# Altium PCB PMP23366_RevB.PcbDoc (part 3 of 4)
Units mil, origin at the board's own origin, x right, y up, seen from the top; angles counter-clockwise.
Board outline 6500 x 4250 mil, 4 copper layers (Top Layer 1, Inner Layer 2, Inner Layer 3, Bottom Layer 1), stack 75.824 mil thick; 370 components, 218 nets, 1221 pads, 351 vias.
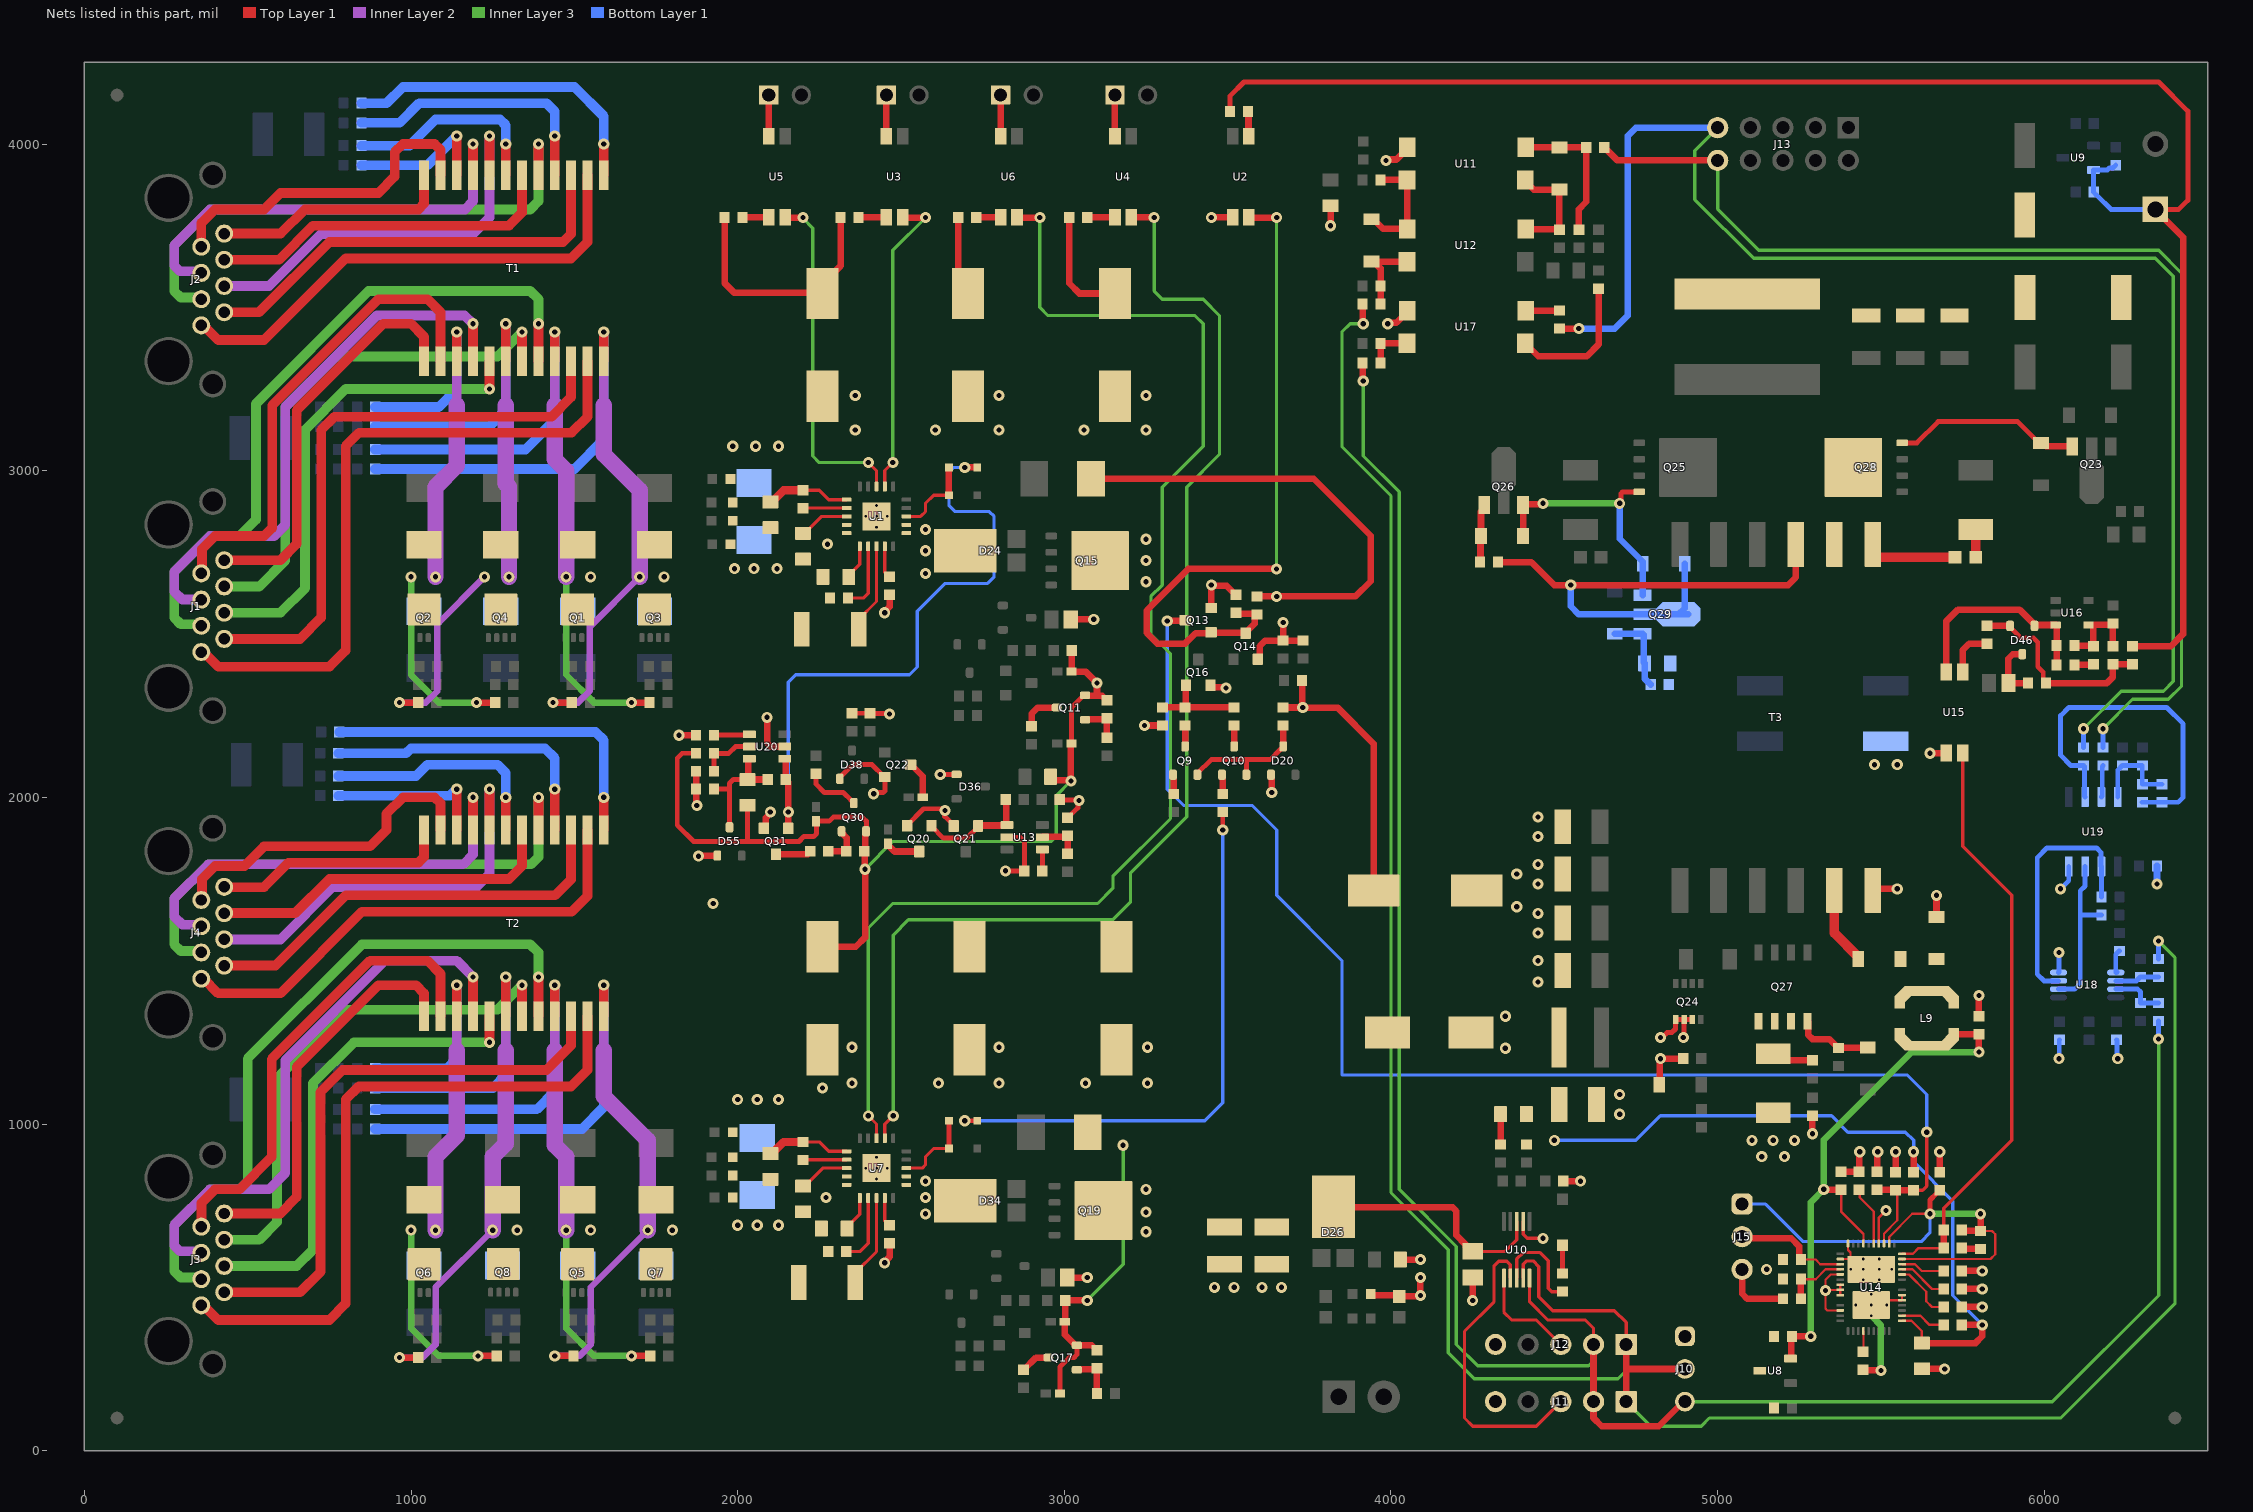
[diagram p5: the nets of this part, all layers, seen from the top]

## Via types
v1: diameter 34, hole 16, Top Layer 1 to Bottom Layer 1, tented both sides, 307 vias
v2: diameter 19.68, hole 7.87, Top Layer 1 to Bottom Layer 1, 23 vias
v3: diameter 34, hole 16, Top Layer 1 to Bottom Layer 1, 21 vias

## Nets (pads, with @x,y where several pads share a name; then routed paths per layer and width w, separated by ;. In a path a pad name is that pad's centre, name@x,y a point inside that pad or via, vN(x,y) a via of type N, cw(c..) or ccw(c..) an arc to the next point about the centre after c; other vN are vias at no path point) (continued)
NetC73_1: C73.1 C94.2 D51.1 Q28.5 Q28.6 Q28.7 Q28.8 Q28.9@5415.39,3010 Q29.2 Q29.4 R92.2 R132.1 T3.7 T3.8 T3.9 | length 1934.9
  Top Layer 1 w20: R92.2@4327.56,2720 4430,2720 4500,2650 v1(4550.47,2650) 5215.91,2650 5239.06,2673.15 T3.9@5239.06,2774.53
  Top Layer 1 w30: T3.7@5475.28,2774.53 5475.28,2745.59 5485.87,2735 C73.1@5727.01,2735
  Bottom Layer 1 w20: v1(4550.47,2650) 4550,2649.53 4550,2585 4575,2560 Q29.2@4778.07,2560 Q29.4@4880.43,2560 ; D51.1@4899.47,2715 4899.47,2579.04 Q29.4@4880.43,2560 ; Q29.4@4909.96,2560 Q29.4@4880.43,2560
NetC73_2: C73.2 R96.1 | length 85
  Top Layer 1 w30: C73.2@5790,2735 R96.1@5790,2820
NetC76_1: C76.1 U14.33 | length 136.6
  Top Layer 1 w7: U14.33@5564.49,570.87 5604.13,570.87 5625,550 C76.1@5692.44,550
NetC79_1: C79.1 J15.2 U14.3 | length 355.9
  Top Layer 1 w7: C79.1@5255,585 5300,585 5314.13,570.87 U14.3@5375.51,570.87
  Top Layer 1 w20: J15.2@5075,655 5080,650 5225,650 5249.25,625.75 5249.25,590.75 C79.1@5255,585
NetC82_2: C82.2 U14.40 | length 183.4
  Top Layer 1 w7: C82.2@5433,798.7 5435,796.71 5435,775.15 5477.87,732.28 U14.40@5477.87,633.86
NetC83_1: C83.1 C85.1 R104.2 R111.2 U16.4 | length 253.6
  Top Layer 1 w20: C83.1@6092.56,2465 6093.78,2463.78 6148.78,2463.78 C85.1@6150,2462.56 6150,2524.53 6153.9,2528.43 6205.98,2528.43 R111.2@6210,2532.44 R104.2@6210,2462.56
NetC83_2: C83.2 D46.1 R109.1 U15.2 U16.3 | length 651.1
  Top Layer 1 w20: U15.2@5700,2384.02 5699.44,2384.57 5699.44,2538.35 5736.1,2575 5923.94,2575 5970,2528.94 D46.1@5970,2525 ; D46.1@5971.81,2527.6 U16.3@6034.8,2527.6 6036.61,2527.6 6037.44,2526.77 C83.2@6037.44,2465 R109.1@6037.44,2405
NetC84_1: C84.1 R103.1 | length 58.5
  Top Layer 1 w20: C84.1@5747.56,620 5748.84,618.72 5803.72,618.72 R103.1@5805,617.44
NetC84_2: C84.2 R105.1 U14.35 U15.4 | length 1799.3
  Top Layer 1 w7: U14.35@5564.49,602.36 5597.36,602.36 5615,620 C84.2@5692.44,620
  Top Layer 1 w10: R105.1@5692.44,675 5692.44,742.44 5900,950 5900,1700 5750,1850 U15.4@5750,2135.98
  Top Layer 1 w20: C84.2@5692.44,620 R105.1@5692.44,675
NetC85_2: C85.2 R109.2 | length 58.5
  Top Layer 1 w20: R109.2@6092.56,2405 6093.78,2406.22 6148.78,2406.22 C85.2@6150,2407.44
NetC86_2: C86.2 D46.3 R107.2 | length 182.8
  Top Layer 1 w20: D46.3@5932.6,2438.39 5903.78,2438.39 5890,2424.61 C86.2@5890,2350 R107.2@5949.88,2350
NetC89_2: C89.2 D55.3 R130.2 R134.1 U20.6 | length 371.1
  Top Layer 1 w15: C89.2@1927.56,2025 1974.91,2025 1975,2025.09 ; D55.3@1975,1908.31 1975,2025.09 ; R130.2@2030.32,2054.69 1986.5,2054.69 1975,2043.19 1975,2025.09
  Top Layer 1 w20: U20.6@2035.87,2118.15 2034.74,2118.15 2032.93,2116.34 2032.93,2057.3 2030.32,2054.69 2092.13,2054.69 R134.1@2092.44,2055
NetC91_2: C91.2 R118.1 R123.2 R124.2 U19.8 | length 280.4
  Bottom Layer 1 w15: U19.8@6225,2001.3 6225,2083.43 6239.02,2097.44 R118.1@6240,2097.44 C91.2@6300,2097.44 R123.2@6300,2040 R124.2@6360,2040
NetC92_1: C92.1 U20.4 | length 109.5
  Top Layer 1 w15: C92.1@1927.56,2190 1929.04,2191.48 2034.39,2191.48 U20.4@2035.87,2192.95
NetC93_1: C93.1 U13.4 | length 65.6
  Top Layer 1 w15: C93.1@2932.56,1775 C93.1@2932.56,1775 2932.61,1840.5 U13.4@2932.66,1840.55
NetC94_1: C94.1 D52.1 Q29.1 R132.2 | length 251.8
  Bottom Layer 1 w20: D52.1@4685,2500.53 4685.21,2500.74 4770.2,2500.74 4773.27,2497.67 4773.27,2413.07 R132.2@4776.34,2410 4776.34,2363.54 4788.15,2351.73 4789.13,2351.73 4794.88,2345.98 C94.1@4794.88,2345
NetD20_3: D20.3 Q9.2 Q10.2 R33.1 | length 400.7
  Top Layer 1 w15: Q9.2@3407.4,2069.25 3407.4,2073.19 3449.88,2115.67 3555,2115.67 ; Q10.2@3557.4,2069.25 3557.4,2113.27 3555,2115.67 ; D20.3@3661.75,2147.62 3629.8,2115.67 3555,2115.67
  Top Layer 1 w20: D20.3@3670,2155.87 R33.1@3670,2220
NetD22_1: D22.1 D53.1 U1.13 | length 256.7
  Top Layer 1 w10: U1.13@2516.54,2860 2560,2860 2575,2875 2575,2900 2600,2925 D22.1@2646.69,2925
  Top Layer 1 w20: D22.1@2646.69,2925 D53.1@2646.69,3010
NetD31_1: D31.1 D54.1 U7.13 | length 254.7
  Top Layer 1 w10: U7.13@2516.54,865 2565,865 2575,875 2575,900 2600,925 D31.1@2646.69,925
  Top Layer 1 w15: D31.1@2646.69,925 D54.1@2646.69,1010
NetD35_1: D35.1 R83.1 | length 89.2
  Top Layer 1 w15: R83.1@4525,540 D35.1@4525,629.21
NetD39_2: D39.2 Q23.3 Q28.4 | length 579
  Top Layer 1 w15: Q28.4@5565,3085 5610,3085 5675,3150 5918.46,3150 5984,3084.47 D39.2@5990,3084.47
  Top Layer 1 w20: D39.2@5990,3084.47 5996,3084.47 6005.67,3074.8 Q23.3@6085.94,3074.8
NetD42_1: D42.1 D51.2 Q25.4 Q26.3 Q29.3 | length 793.5
  Top Layer 1 w15: v1(4700,2900) 4703.64,2903.64 4703.64,2929.85 4708.79,2935 Q25.4@4760,2935
  Top Layer 1 w20: D42.1@4404.47,2800 4404.26,2800.21 4404.26,2894.99 Q26.3@4404.06,2895.2 4406.46,2897.6 4462.6,2897.6 v1(4465,2900)
  Inner Layer 3 w20: v1(4465,2900) v1(4700,2900)
  Bottom Layer 1 w20: v1(4700,2900) 4700,2791.54 4770.53,2721 D51.2@4770.53,2715 4770.36,2714.83 4770.36,2619.22 Q29.3@4770.2,2619.06
NetD42_2: D42.2 Q26.1 R92.1 | length 180.8
  Top Layer 1 w20: R92.1@4272.44,2720 4273.99,2721.55 4273.99,2798.45 D42.2@4275.53,2800 4275.53,2874.94 4285.94,2885.35 Q26.1@4285.94,2895.2
NetD43_2: D43.2 Q27.4 R94.2 | length 243.3
  Top Layer 1 w20: Q27.4@5275,1314.88 5277.01,1312.87 5277.01,1272.99 5290,1260 5341.57,1260 5369.02,1232.56 5369.97,1233.51 5459.05,1233.51 D43.2@5460,1234.47
NetD44_1: D44.1 D45.1 L9.2
NetD44_2: D44.2 T3.5 | length 240.9
  Top Layer 1 w30: T3.5@5357.17,1715.47 5357.17,1584.37 5430.53,1511 D44.2@5430.53,1505
NetD46_2: D46.2 R101.2 R104.1 R106.2 R107.1 | length 625
  Top Layer 1 w15: D46.2@5895.2,2525 5895.2,2521.06 5927.68,2488.58 5966.42,2488.58 5980,2475 5980,2400 5996.75,2383.25 5996.75,2358.25 R107.1@6005,2350
  Top Layer 1 w20: R106.2@5825,2525 D46.2@5895.2,2525 ; R107.1@6005,2350 6191.57,2350 6210,2368.43 R104.1@6210,2407.44 R101.2@6270,2407.44
NetD47_1: D47.1 Q22.3 | length 116.6
  Top Layer 1 w20: Q22.3@2529.37,2100 2531.34,2100 2566.65,2064.69 D47.1@2566.65,2000
NetD48_1: D48.1 Q20.3 | length 108.4
  Top Layer 1 w20: D48.1@2460,1858.35 2460,1854.41 2480.2,1834.21 Q20.3@2556.12,1834.21
NetD49_1: D49.1 R77.1 U11.1 U12.4 | length 346.3
  Top Layer 1 w20: U11.1@4411.22,3890 4411.22,3886.06 4436.75,3860.53 D49.1@4515.61,3860.53 R77.1@4515.61,3737.56 4514.39,3738.78 4413.43,3738.78 U12.4@4412.2,3740
NetD49_2: D49.2 R78.1 R79.1 U11.2 | length 448.5
  Top Layer 1 w20: U11.2@4412.2,3990 4412.47,3989.73 4515.34,3989.73 D49.2@4515.61,3989.47 4515.88,3989.73 4597.79,3989.73 R79.1@4598.05,3990 4598.05,3823.05 4575,3800 4575,3738.17 R78.1@4575.61,3737.56
NetD50_1: D50.1 R76.2 U11.4 U12.1 | length 352.9
  Top Layer 1 w20: D50.1@3940.61,3769.47 3946.61,3769.47 3976.08,3740 U12.1@4050,3740 4049.51,3740.49 4049.51,3889.51 U11.4@4049.02,3890 R76.2@3968.17,3890
NetD50_2: D50.2 R80.2 R81.1 U12.2 | length 247.7
  Top Layer 1 w20: D50.2@3940.61,3640.53 3946.61,3640.53 D50.2@3946.88,3640.27 ; R81.1@3968.17,3510 R80.2@3968.17,3565 3968.17,3618.98 D50.2@3946.88,3640.27 ; U12.2@4049.02,3640 4048.75,3640.27 D50.2@3946.88,3640.27
NetJ1_1: J1.1 T1.23 | length 2053.6
  Top Layer 1 w30: J1.1@357.91,2444.84 364.71,2444.84 409.55,2400 750,2400 800,2450 800,3075 841.3,3116.3 1491.3,3116.3 1540,3165 T1.23@1540,3334.92
NetJ1_2: J1.2 T1.22 | length 1815.3
  Top Layer 1 w30: J1.2@427.99,2485 660,2485 725,2550 725,3125 765,3165 1430,3165 1490,3225 T1.22@1490,3334.92
NetJ1_3: J1.3 T1.20 | length 2112.8
  Top Layer 1 w30: T1.20@1390,3334.92 v1(1390,3450)
  Inner Layer 3 w30: J1.3@357.91,2525.16 353.11,2529.96 295.04,2529.96 275,2550 275,2690 385,2800 475,2800 525,2850 525,3205 870,3550 1365,3550 1390,3525 v1(1390,3450)
NetJ1_4: J1.4 T1.17 | length 1464.6
  Top Layer 1 w30: v1(1240,3250) T1.17@1240,3334.92
  Inner Layer 3 w30: J1.4@427.99,2565.31 600.32,2565.31 675,2640 675,3125 800,3250 v1(1240,3250)
NetJ1_5: J1.5 T1.16 | length 1730.4
  Top Layer 1 w30: T1.16@1190,3334.92 v1(1190,3450)
  Inner Layer 2 w30: J1.5@357.91,2605.47 299.53,2605.47 275,2630 275,2690 385,2800 581.42,2800 615,2833.58 615,3195 895,3475 1163.92,3475 1188.92,3450 v1(1190,3450)
NetJ1_6: J1.6 T1.19 | length 1600.2
  Top Layer 1 w30: T1.19@1340,3334.92 v1(1340,3425)
  Inner Layer 3 w30: J1.6@427.99,2645.63 535.63,2645.63 615,2725 615,3195 770,3350 1265,3350 v1(1340,3425)
NetJ1_7: J1.7 T1.14 | length 1508.3
  Top Layer 1 w30: J1.7@357.91,2685.79 360,2687.87 360,2760 400,2800 550,2800 575,2825 575,3200 900,3525 1050,3525 1090,3485 T1.14@1090,3334.92
NetJ1_8: J1.8 T1.13 | length 1243.7
  Top Layer 1 w30: J1.8@427.99,2725.94 600.94,2725.94 650,2775 650,3185 915,3450 1000,3450 1040,3410 T1.13@1040,3334.92
NetJ2_1: J2.1 T1.2 | length 1529.9
  Top Layer 1 w30: J2.1@357.91,3444.84 364.71,3444.84 409.55,3400 550,3400 800,3650 1490,3650 1540,3700 T1.2@1540,3905
NetJ2_2: J2.2 T1.3 | length 1341.6
  Top Layer 1 w30: J2.2@427.99,3485 535,3485 750,3700 1465.35,3700 1490,3724.65 T1.3@1490,3905
NetJ2_3: J2.3 T1.5 | length 1674.1
  Top Layer 1 w30: T1.5@1390,3905 v1(1390,4000)
  Inner Layer 3 w30: J2.3@357.91,3525.16 353.11,3529.96 295.04,3529.96 275,3550 275,3690 385,3800 1365,3800 1390,3825 v1(1390,4000)
NetJ2_4: J2.4 T1.8 | length 1268.9
  Top Layer 1 w30: T1.8@1240,3905 v1(1240,4025)
  Inner Layer 2 w30: J2.4@427.99,3565.31 565.32,3565.31 725,3725 1190,3725 1240,3775 v1(1240,4025)
NetJ2_5: J2.5 T1.9 | length 1395.3
  Top Layer 1 w30: T1.9@1190,3905 v1(1190,4000)
  Inner Layer 2 w30: J2.5@357.91,3605.47 353.11,3610.28 292.57,3610.28 275,3627.85 275,3690 385,3800 1165,3800 1190,3825 v1(1190,4000)
NetJ2_6: J2.6 T1.6 | length 1086.8
  Top Layer 1 w30: J2.6@427.99,3645.63 595.63,3645.63 700,3750 1300,3750 1340,3790 T1.6@1340,3905
NetJ2_7: J2.7 T1.11 | length 1033.1
  Top Layer 1 w30: J2.7@357.91,3685.79 357.91,3757.91 400,3800 550,3800 600,3850 900,3850 950,3900 950,3975 975,4000 1072.43,4000 1090,3982.43 T1.11@1090,3905
NetJ2_8: J2.8 T1.12 | length 737.4
  Top Layer 1 w30: J2.8@427.99,3725.94 600.94,3725.94 675,3800 1022.43,3800 1040,3817.57 T1.12@1040,3905
NetJ3_1: J3.1 T2.23 | length 2048.6
  Top Layer 1 w30: J3.1@357.91,444.84 364.71,444.84 409.55,400 750,400 800,450 800,1075 840,1115 1490,1115 1540,1165 T2.23@1540,1329.96
NetJ3_2: J3.2 T2.22 | length 1786.9
  Top Layer 1 w30: J3.2@427.99,485 660,485 722.44,547.44 722.44,1097.44 790,1165 1415,1165 1490,1240 T2.22@1490,1329.96
NetJ3_3: J3.3 T2.20 | length 2129.5
  Top Layer 1 w30: T2.20@1390,1329.96 v1(1390,1450)
  Inner Layer 3 w30: J3.3@357.91,525.16 353.11,529.96 295.04,529.96 275,550 275,690 385,800 475,800 500,825 500,1200 850,1550 1365,1550 1390,1525 v1(1390,1450)
NetJ3_4: J3.4 T2.17 | length 1474.6
  Top Layer 1 w30: v1(1240,1250) T2.17@1240,1329.96
  Inner Layer 3 w30: J3.4@427.99,565.32 428.31,565 650,565 700,615 700,1125 825,1250 v1(1240,1250)
NetJ3_5: J3.5 T2.16 | length 1747.7
  Top Layer 1 w30: T2.16@1190,1329.96 v1(1190,1450)
  Inner Layer 2 w30: J3.5@357.91,605.47 353.11,610.28 292.57,610.28 275,627.85 275,690 385,800 565,800 615,850 615,1195 920,1500 1140,1500 v1(1190,1450)
NetJ3_6: J3.6 T2.19 | length 1587.6
  Top Layer 1 w30: T2.19@1340,1329.96 v1(1340,1425)
  Inner Layer 3 w30: J3.6@427.99,645.63 535.63,645.63 590,700 590,1140 800,1350 1265,1350 v1(1340,1425)
NetJ3_7: J3.7 T2.14 | length 1433.9
  Top Layer 1 w30: J3.7@357.91,685.79 358.35,686.22 358.35,758.35 400,800 475,800 573.43,898.43 573.43,1198.43 875,1500 1050,1500 1090,1460 T2.14@1090,1329.96
NetJ3_8: J3.8 T2.13 | length 1215.7
  Top Layer 1 w30: J3.8@427.99,725.94 600,725.94 650,775.94 650,1175 900,1425 1015,1425 1040,1400 T2.13@1040,1329.96
NetJ4_1: J4.1 T2.2 | length 1526.3
  Top Layer 1 w30: J4.1@357.91,1444.84 364.71,1444.84 409.55,1400 600,1400 850,1650 1492.26,1650 1540,1697.74 T2.2@1540,1900.04
NetJ4_2: J4.2 T2.3 | length 1322.4
  Top Layer 1 w30: J4.2@427.99,1485 585,1485 800,1700 1441.08,1700 1490,1748.92 T2.3@1490,1900.04
NetJ4_3: J4.3 T2.5 | length 1683.4
  Top Layer 1 w30: T2.5@1390,1900.04 v1(1390,2000)
  Inner Layer 3 w30: J4.3@357.91,1525.16 353.11,1529.96 295.04,1529.96 275,1550 275,1690 380,1795 1367.43,1795 1390,1817.57 v1(1390,2000)
NetJ4_4: J4.4 T2.8 | length 1279.9
  Top Layer 1 w30: T2.8@1240,1900.04 v1(1240,2025)
  Inner Layer 2 w30: J4.4@427.99,1565.32 428.31,1565 600,1565 760,1725 1200,1725 1240,1765 v1(1240,2025)
NetJ4_5: J4.5 T2.9 | length 1396
  Top Layer 1 w30: T2.9@1190,1900.04 v1(1190,2000)
  Inner Layer 2 w30: J4.5@357.91,1605.47 353.11,1610.28 299.72,1610.28 275,1635 275,1690 380,1795 1160,1795 1190,1825 v1(1190,2000)
NetJ4_6: J4.6 T2.6 | length 1081.8
  Top Layer 1 w30: J4.6@427.99,1645.63 645.63,1645.63 750,1750 1300,1750 1340,1790 T2.6@1340,1900.04
NetJ4_7: J4.7 T2.11 | length 1017.6
  Top Layer 1 w30: J4.7@357.91,1685.79 360,1687.87 360,1750 400,1790 490,1790 550,1850 875,1850 925,1900 925,1950 975,2000 1072.43,2000 1090,1982.43 T2.11@1090,1900.04
NetJ4_8: J4.8 T2.12 | length 733.2
  Top Layer 1 w30: J4.8@427.99,1725.94 428.94,1725 550,1725 625,1800 1022.43,1800 1040,1817.57 T2.12@1040,1900.04
NetJ5_1: J5.1 U3.4 | length 126
  Top Layer 1 w20: U3.4@2455,4024.02 J5.1@2455,4150
NetJ6_1: J6.1 U4.4 | length 126
  Top Layer 1 w20: U4.4@3155,4024.02 J6.1@3155,4150
NetJ7_1: J7.1 U5.4 | length 126
  Top Layer 1 w20: U5.4@2095,4024.02 J7.1@2095,4150
NetJ8_1: J8.1 U6.4 | length 126
  Top Layer 1 w20: U6.4@2805,4024.02 J8.1@2805,4150
NetJ11_3: J11.3 U10.2 | length 940.8
  Top Layer 1 w10: U10.2@4365.31,528.39 4365.31,569.68 4355,580 4330,580 4315,565 4315,454.84 4225,364.84 4225,100 4250,75 4445,75 J11.3@4520,150
NetJ12_3: J12.3 U10.1 | length 319.5
  Top Layer 1 w10: U10.1@4345.63,528.39 4345.63,424.37 4370,400 4445,400 J12.3@4520,325
NetJ15_3: J15.3 R100.1 | length 206.1
  Top Layer 1 w20: J15.3@5075,555 5075,480 5090,465 R100.1@5199.88,465
NetQ9_1: Q9.1 R38.2 | length 60.1
  Top Layer 1 w20: Q9.1@3332.6,2069.25 3332.6,2065.31 3335,2062.91 R38.2@3335,2010.12
NetQ9_3: Q9.3 R42.1 | length 64.1
  Top Layer 1 w20: Q9.3@3370,2155.87 R42.1@3370,2220
NetQ10_1: Q10.1 R39.2 | length 60.1
  Top Layer 1 w20: Q10.1@3482.6,2069.25 3482.6,2065.31 3485,2062.91 R39.2@3485,2010.12
NetQ10_3: Q10.3 R43.2 | length 64.1
  Top Layer 1 w20: Q10.3@3520,2155.87 R43.2@3520,2220
NetQ11_1: Q11.1 R35.1 R37.1 | length 122.7
  Top Layer 1 w20: Q11.1@3063.31,2237.6 3065.12,2239.41 3127.28,2239.41 3130,2236.69 R37.1@3130,2182.56
NetQ11_3: Q11.3 R41.2 | length 123.2
  Top Layer 1 w20: R41.2@2900,2217.56 2900,2256.3 2918.7,2275 Q11.3@2976.69,2275
NetQ13_1: Q13.1 Q14.3 R45.1 R51.2 U2.4 | length 2151
  Top Layer 1 w10: U2.4@3565,3775.98 U2.4@3565.98,3775 ; v1(3649.33,2699.29) v1@3650.71,2699.29
  Top Layer 1 w20: R51.2@3525,2565 3527.5,2562.5 3587.5,2562.5 R45.1@3590,2560 3589.02,2560 3583.27,2554.25 3583.27,2532.17 3554.65,2503.54 3450.98,2503.54 Q13.1@3449.37,2505.16 3446.93,2502.72 3401.65,2502.72 3369.61,2470.67 3284.74,2470.67 3252.14,2503.27 3252.14,2571.87 3379.56,2699.29 v1(3649.33,2699.29) ; U2.4@3565.98,3775 v1(3650,3775)
  Inner Layer 3 w10: v1(3649.33,2699.29) 3649.33,3774.33 v1(3650,3775)
NetQ16_1: Q16.1 R42.2 R43.1 R54.2 | length 289.1
  Top Layer 1 w20: R54.2@3300,2275.12 R42.2@3370,2275.12 ; Q16.1@3372.6,2343.19 3371.3,2341.89 3371.3,2276.42 R42.2@3370,2275.12 ; R43.1@3520,2275.12 R42.2@3370,2275.12
NetQ17_1: Q17.1 R59.1 R62.1 | length 141.1
  Top Layer 1 w20: Q17.1@3038.31,247.6 3040.12,249.41 3096.97,249.41 R59.1@3099.94,252.38 ; R62.1@3099.88,175 3099.94,175.06 R59.1@3099.94,252.38 ; R59.1@3100,252.44 R59.1@3099.94,252.38
NetQ17_3: Q17.3 R63.2 | length 92.2
  Top Layer 1 w20: R63.2@2875,247.56 2875.98,247.56 2913.43,285 Q17.3@2951.69,285
NetQ20_1: Q20.1 Q21.1 R86.2 U13.1 | length 343.4
  Top Layer 1 w15: Q20.1@2593.52,1912.95 2593.52,1910.98 2629.51,1875 2700.57,1875 2735.92,1910.35 Q21.1@2735.92,1912.32
  Top Layer 1 w20: Q21.1@2735.92,1912.32 2737.44,1913.84 2822.87,1913.84 2822.68,1914.03 2822.68,1991.24 R86.2@2820.96,1992.95
NetQ27_1: Q27.1 Q27.2 Q27.3 R98.2 R99.1 | length 128.3
  Top Layer 1 w20: R99.1@5170,1215 5190,1195 R98.2@5290,1195
NetQ30_1: Q30.1 R131.1 R133.1 | length 122.6
  Top Layer 1 w20: R133.1@2277.56,1835 R131.1@2332.44,1835 2333.46,1836.02 2333.46,1876.67 2318.13,1892.01 Q30.1@2318.13,1895.94
NetQ30_3: Q30.3 R85.2 | length 174.1
  Top Layer 1 w15: R85.2@2240,2072.44 2240,2040 2265,2015 2323.09,2015 2347.28,1990.81 2351.22,1990.81 2355.53,1986.5 Q30.3@2355.53,1982.56
NetQ31_3: Q31.3 R133.2 | length 109
  Top Layer 1 w20: Q31.3@2117.6,1826.26 2214.68,1826.26 2222.44,1834.02 R133.2@2222.44,1835
NetR1_2: R1.2 T1.1 | length 979.4
  Top Layer 1 w30: T1.1@1590,3905 v1(1590,4000)
  Bottom Layer 1 w30: R1.2@848.62,4125 925,4125 975,4175 1500,4175 1590,4085 v1(1590,4000)
NetR2_2: R2.2 T1.4 | length 821.6
  Top Layer 1 w30: T1.4@1440,3905 v1(1440,4025)
  Bottom Layer 1 w30: R2.2@848.62,4065 965,4065 1025,4125 1415,4125 1440,4100 v1(1440,4025)
NetR11_2: R11.2 T1.7 | length 634.2
  Top Layer 1 w30: T1.7@1290,3905 v1(1290,4000)
  Bottom Layer 1 w30: R11.2@848.62,3995 995,3995 1075,4075 1272.43,4075 1290,4057.43 v1(1290,4000)
NetR12_2: R12.2 T1.10 | length 448.7
  Top Layer 1 w30: T1.10@1140,3905 v1(1140,4025)
  Bottom Layer 1 w30: R12.2@848.62,3935 1050,3935 v1(1140,4025)
NetR17_2: R17.2 T2.1 | length 1095.3
  Top Layer 1 w30: T2.1@1590,1900.04 v1(1590,2000)
  Bottom Layer 1 w30: R17.2@780,2200 1565,2200 1590,2175 v1(1590,2000)
NetR18_2: R18.2 T2.4 | length 901
  Top Layer 1 w30: T2.4@1440,1900.04 v1(1440,2025)
  Bottom Layer 1 w30: R18.2@777.56,2135 985,2135 1000,2150 1410,2150 1440,2120 v1(1440,2025)
NetR27_2: R27.2 T2.7 | length 712.3
  Top Layer 1 w30: T2.7@1290,1900.04 v1(1290,2000)
  Bottom Layer 1 w30: R27.2@777.56,2065 1015,2065 1050,2100 1265,2100 1290,2075 v1(1290,2000)
NetR28_2: R28.2 T2.10 | length 495.7
  Top Layer 1 w30: T2.10@1140,1900.04 v1(1140,2025)
  Bottom Layer 1 w30: R28.2@777.56,2005 1118.92,2005 1138.92,2025 v1(1140,2025)
NetR34_1: R34.1 U1.2 | length 133.8
  Top Layer 1 w10: R34.1@2200,2884.88 2200.71,2885.59 U1.2@2333.46,2885.59
NetR40_1: R40.1 U1.9 | length 100
  Top Layer 1 w10: U1.9@2450.59,2768.46 2450.59,2688.43 2464.02,2675 R40.1@2465,2675
NetR44_1: R44.1 U1.8 | length 276.2
  Top Layer 1 w10: R44.1@2370,2515 2370,2544.53 2425,2599.53 U1.8@2425,2768.46
NetR46_2: R46.2 U1.7 | length 211.9
  Top Layer 1 w10: R46.2@2337.56,2610 2385,2610 2399.41,2624.41 U1.7@2399.41,2768.46
NetR47_2: R47.2 U1.3 | length 155
  Top Layer 1 w10: R47.2@2200,2808.07 2204.92,2808.07 2256.85,2860 U1.3@2333.46,2860
NetR48_2: R48.2 U1.6 | length 107.5
  Top Layer 1 w10: R48.2@2340,2675 2340,2679.92 2373.82,2713.74 U1.6@2373.82,2768.46
NetR53_1: R53.1 U2.1 | length 77
  Top Layer 1 w20: R53.1@3562.56,4100 3563.78,4098.78 3563.78,4025.24 U2.1@3565,4024.02
NetR55_2: R55.2 U3.1 | length 85.4
  Top Layer 1 w20: R55.2@2370,3775 2370.49,3775.49 2454.51,3775.49 U3.1@2455,3775.98
NetR56_2: R56.2 U4.1 | length 85.4
  Top Layer 1 w20: R56.2@3070,3775 3070.49,3775.49 3154.51,3775.49 U4.1@3155,3775.98
NetR57_2: R57.2 U5.1 | length 80.4
  Top Layer 1 w20: R57.2@2015,3775 2015.49,3775.49 2094.51,3775.49 U5.1@2095,3775.98
NetR58_2: R58.2 U6.1 | length 75.4
  Top Layer 1 w20: R58.2@2730,3775 2730.49,3775.49 2804.51,3775.49 U6.1@2805,3775.98
NetR60_1: R60.1 U7.2 | length 133.8
  Top Layer 1 w10: R60.1@2200,889.88 2200.71,890.59 U7.2@2333.46,890.59
NetR64_1: R64.1 U7.9 | length 90
  Top Layer 1 w10: U7.9@2450.59,773.46 2450.59,703.43 2464.02,690 R64.1@2465,690
NetR65_1: R65.1 U7.8 | length 285.4
  Top Layer 1 w10: R65.1@2360,515 2360,544.53 2425,609.53 U7.8@2425,773.46
NetR66_2: R66.2 U7.7 | length 216
  Top Layer 1 w10: R66.2@2332.56,610 2375,610 2399.41,634.41 U7.7@2399.41,773.46
NetR67_2: R67.2 U7.3 | length 156.2
  Top Layer 1 w10: R67.2@2200,810 2204.92,810 2259.92,865 U7.3@2333.46,865
NetR68_2: R68.2 U7.6 | length 109.5
  Top Layer 1 w10: R68.2@2335,680 2335,684.92 2373.82,723.74 U7.6@2373.82,773.46
NetR82_2: R82.2 R116.1 U17.4 | length 140.8
  Top Layer 1 w20: R116.1@3968.17,3330 R82.2@3968.17,3390 U17.4@4049.02,3390
NetR83_2: R83.2 U10.3 | length 306.2
  Top Layer 1 w10: U10.3@4385,528.39 4385,586.85 4404.45,606.3 4456.5,606.3 4481.3,581.5 4481.3,496.8 4491.71,486.38 4523.94,486.38 R83.2@4525,487.44
NetR87_1: R87.1 R89.2 U13.5 | length 134.1
  Top Layer 1 w20: U13.5@2932.66,1877.95 2934.47,1879.76 3007.32,1879.76 R89.2@3010,1882.44 R87.1@3010,1827.56
NetR100_2: R100.2 R102.1 U14.4 | length 193
  Top Layer 1 w7: R102.1@5255,525 5300,525 5330.12,555.12 U14.4@5375.51,555.12
  Top Layer 1 w20: R100.2@5255,465 R102.1@5255,525
NetR106_1: R106.1 U15.1 | length 149.2
  Top Layer 1 w20: U15.1@5750,2384.02 5750,2450 5769.88,2469.88 R106.1@5825,2469.88
NetR108_2: R108.2 U14.17 | length 64.3
  Top Layer 1 w7: R108.2@5445.06,302.42 5446.38,303.74 U14.17@5446.38,366.14
NetR110_2: R110.2 U14.24 | length 139.7
  Top Layer 1 w7: U14.24@5564.49,413.39 5619.96,413.39 5648.35,385 R110.2@5692.44,385
NetR112_2: R112.2 U14.31 | length 185.9
  Top Layer 1 w7: U14.31@5564.49,539.37 5585.63,539.37 5638.82,486.18 5638.82,457.49 5656.31,440 R112.2@5692.44,440
NetR113_2: R113.2 U14.32 | length 152.9
  Top Layer 1 w7: U14.32@5564.49,555.12 5596.23,555.12 5656.35,495 R113.2@5692.44,495
NetR114_1: R114.1 U17.1 | length 428.7
  Top Layer 1 w20: U17.1@4411.22,3390 4411.22,3386.06 4426.81,3370.47 4430.75,3370.47 4450.55,3350.67 4599.69,3350.67 4635.61,3386.59 R114.1@4635.61,3557.44
NetR115_1: R115.1 U17.2 | length 103.5
  Top Layer 1 w20: U17.2@4412.2,3490 4412.26,3490.06 R115.1@4515.61,3490.12 R115.1@4515.61,3490.12
NetR119_2: R119.2 R127.2 U18.7 | length 168.6
  Bottom Layer 1 w15: U18.7@6218.9,1412.76 6286.21,1412.76 6295,1403.97 R119.2@6295,1370.12 R127.2@6350,1370.12
NetR120_1: R120.1 R129.2 U18.6 | length 135.9
  Bottom Layer 1 w15: U18.6@6218.9,1438.35 6282.36,1438.35 6294.02,1450 R120.1@6295,1450 R129.2@6350,1450
NetR123_1: R123.1 R124.1 R126.1 U19.6 | length 1066.6
  Bottom Layer 1 w15: U19.6@6125,2001.3 6122.5,2003.8 6122.5,2094.94 R126.1@6120,2097.44 6118.75,2096.19 6117.5,2097.44 6081.58,2097.44 6050,2129.02 6050,2250 6075,2275 6375,2275 6425,2225 6425,2000 6409.88,1984.88 R124.1@6360,1984.88 R123.1@6300,1984.88 R123.1@6299.02,1984.88
NetR125_1: R125.1 U19.7 | length 98.2
  Bottom Layer 1 w15: U19.7@6175,2001.3 6177.5,2003.8 6177.5,2094.94 R125.1@6180,2097.44
NetR128_2: R128.2 U18.5 | length 75.3
  Bottom Layer 1 w15: U18.5@6222.6,1465.19 6221.34,1463.94 U18.5@6218.9,1463.94 6218.9,1519.76 6229.02,1529.88 R128.2@6230,1529.88
NetR135_1: R135.1 R136.2 U20.5 | length 172.3
  Top Layer 1 w15: R136.2@1927.56,2080 R135.1@1927.56,2135 1928.11,2134.45 1972.5,2134.45 1993.61,2155.55 U20.5@2035.87,2155.55
PAD_S: R108.1 U14.27 U14.28 U14.47 | length 353.1
  Top Layer 1 w7: v2(5470,445.87) 5484.76,460.63 U14.27@5564.49,460.63 U14.28@5564.49,476.38
  Top Layer 1 w20: R108.1@5445.06,247.3 5446.21,246.15 5498.85,246.15 v1(5500,245)
  Inner Layer 3 w20: v2(5470,413.39) 5500,383.39 v1(5500,245)
  other v2: 5422.76,445.87 5517.24,445.87 5470,478.35
PG1_EN: D53.2 Q31.1 R134.2 U20.1 | length 1999.6
  Top Layer 1 w20: U20.1@2144.13,2118.15 2145.75,2118.15 2147.56,2116.34 R134.2@2147.56,2055 ; Q31.1@2155,1905 v3(2155,1955) R134.2@2155,2046.57 ; v3(2695,3010) D53.2@2733.31,3010
  Bottom Layer 1 w10: v3(2155,1955) 2155,2352.46 2177.54,2375 2525.97,2375 2550,2399.03 2550,2570 2635,2655 2765,2655 2785,2675 2785,2860 2770,2875 2666.19,2875 2646.69,2894.5 2646.69,2995.59 2661.1,3010 v3(2695,3010)
PG2: D54.2 R39.1 | length 1741.1
  Top Layer 1 w15: v3(2695,1010) D54.2@2733.31,1010 ; v3(3485,1900) R39.1@3485,1955
  Bottom Layer 1 w10: v3(2695,1010) 3430,1010 3485,1065 v3(3485,1900)
PGND: C29.1 C31.2 C32.1 C33.1 C36.2 C37.2 C38.2 C39.2 C43.1 C45.2 C46.2 C51.1 C52.1 C53.2 C54.2 C55.1 C56.2 C57.1 C58.2 C59.2 C60.2 C61.2 C74.1 C75.2 C76.2 C77.1 C78.1 C79.2 C80.1 C81.1 C82.1 C90.1 C93.2 C95.2 C96.2 D20.1 D36.1 D38.1 D41.1 D45.2 J10.1 J11.5 J12.5 L6.2 Q13.2 Q14.2 Q15.5 Q15.6 Q15.7 Q15.8 Q15.9@3109.57,2725 Q16.2 Q19.5 Q19.6 Q19.7 Q19.8 Q19.9@3119.57,735 Q20.2 Q21.2 Q22.2 Q24.1 Q24.2 Q24.3 R51.1 R52.1 R54.1 R88.1 R89.1 R91.1 R97.1 R99.2 R102.2 R112.1 R113.1 T3.6 U2.3 U8.3 U10.7 U11.3 U13.2 U14.2 U14.5 U14.7 U14.8 U14.9 U14.11 U14.39 U14.45 U14.46 U15.3 U17.3 U18.4 U19.4 | length 4528.8
  Top Layer 1 w7: U14.11@5375.51,429.13 5335.87,429.13 5330,435 v1(5330,490) ; U14.9@5375.51,476.38 U14.8@5375.51,492.13 ; U14.7@5375.51,507.87 U14.8@5375.51,492.13 ; U14.5@5375.51,539.37 5345.94,539.37 5330,523.43 v1(5330,490) ; U14.2@5375.51,586.61 U14.46@5407.01,586.61 ; U14.45@5399.13,633.86 5399.13,614.17 5407.01,606.3 U14.46@5407.01,586.61 ; v2(5407.01,555.12) U14.46@5407.01,586.61 ; U14.46@5470,555.12 5438.5,586.61 U14.46@5407.01,586.61 ; U14.39@5493.62,633.86 5493.62,713.62 v1(5515,735) ; v1(5330,490) 5331.69,491.69 5375.07,491.69 U14.8@5375.51,492.13
  Top Layer 1 w10: U10.7@4404.69,701.61 4404.69,662.56 4417.24,650 v1(4465,650)
  Top Layer 1 w15: D38.1@2312.6,2056.69 2312.6,2060.63 2351.97,2100 2411.26,2100 2448.66,2062.6 Q22.2@2450.63,2062.6 2450.63,2019.79 2445.48,2014.64 2419.85,2014.64 v3(2416.21,2011) ; C56.2@2350,2257.56 R88.1@2405,2257.56 2406.28,2256.28 2463.72,2256.28 v3(2465,2255) ; Q20.2@2518.72,1912.95 2518.72,1914.92 2568.8,1965 2630,1965 2633.64,1961.36 2633.64,1941.78 2661.12,1914.29 Q21.2@2661.12,1912.32 ; v3(2620,2070) 2620.18,2070.18 2670.04,2070.18 D36.1@2670.22,2070.35 ; v3(2820,1775) C93.2@2877.44,1775 2878.52,1776.08 2878.52,1865 2865.57,1877.95 U13.2@2824.39,1877.95 ; C55.1@2986.08,1992.95 2987.56,1991.48 3043.52,1991.48 v3(3045,1990) 3041.36,1986.36 3041.36,1967.94 3010.98,1937.56 R89.1@3010,1937.56 ; v1(4825,1265) 4830.14,1265 4845.14,1280 4860,1280 4870.85,1290.85 4870.85,1319.11 Q24.1@4871.61,1319.88 Q24.2@4897.2,1319.88 ; v1(4895,1265) 4896.44,1266.44 4896.44,1319.11 Q24.2@4897.2,1319.88 ; Q24.3@4922.8,1319.88 Q24.2@4897.2,1319.88
  Top Layer 1 w20: C43.1@3009.06,530 v1(3070,530) ; C29.1@3019.53,2545 v1(3090,2545) ; v1(3245,2220) R54.1@3300,2220 ; Q16.2@3447.4,2343.19 3452.91,2337.68 3492.32,2337.68 v1(3495,2335) ; Q13.2@3449.37,2579.96 3449.69,2580.28 3449.69,2649.69 v1(3450,2650) 3452.68,2647.32 3496.81,2647.32 3504.3,2639.83 3524.02,2620.12 R51.1@3525,2620.12 ; v1(3450,3775) 3450.49,3775.49 3514.51,3775.49 U2.3@3515,3775.98 ; Q14.2@3592.4,2423.19 3598.15,2428.94 3598.15,2462.95 3615.31,2480.12 C31.2@3670,2480.12 ; D20.1@3632.6,2069.25 3634.41,2067.44 3634.41,2059.88 3635,2059.29 v1(3635,2015) ; v1(3670,2535) C31.2@3670,2480.12 ; R52.1@3730,2480.12 C31.2@3670,2480.12 ; v1(3815,3750) C51.1@3815,3811.26 ; C39.2@3938,480 3942.25,475.75 4020.75,475.75 L6.2@4025,471.5 4026.75,473.25 4088.25,473.25 v1(4090,475) v1(4090,530) ; v1(3985,3950) 3987.68,3952.68 4016.62,3952.68 4050,3986.06 U11.3@4050,3990 ; v1(3990,3450) 3992.68,3452.68 4016.62,3452.68 4050,3486.06 U17.3@4050,3490 ; C38.2@4028.74,585 v1(4090,585) ; v1(4250,460) C57.1@4250,530 ; C54.2@4527.56,825 v1(4580,825) ; D41.1@4821.06,1120 4823.03,1121.97 4823.03,1198.03 v1(4825,1200) R91.1@4894.88,1200 ; v1(5290,970) C78.1@5290,1024.88 ; C74.1@5378,853.82 C82.1@5433,853.82 5434,854.82 5434,914 v1(5435,915) ; T3.6@5475.28,1715.47 5479.8,1720 v1(5550,1720) ; R97.1@5488,853.82 5489,854.82 5489,914 v3(5490,915) ; C96.2@5545,852.56 v3(5545,915) ; C75.2@5625,250.63 5625.31,250.32 5694.69,250.32 v1(5695,250) ; v1(5650,2135) 5650.49,2135.49 5699.51,2135.49 U15.3@5700,2135.98 ; D45.2@5670,1633.94 v1(5670,1700) ; C81.1@5680,852.56 v1(5680,915) ; R112.1@5747.56,440 v1(5810,440) ; R113.1@5747.56,495 v1(5810,495) ; C76.2@5747.56,550 5747.72,550.16 5809.84,550.16 v1(5810,550.33) ; C80.1@5800,1330.12 v1(5800,1393.57)
  Bottom Layer 1 w15: U18.4@6043.7,1463.94 6045,1465.19 v1(6045,1525) ; v1(6045,1200) 6045.65,1200.65 6045.65,1257.34 C53.2@6046.3,1257.99 ; v1(6050,1720) 6075,1745 U19.4@6075,1788.7 ; C52.1@6221.3,1257.99 6223.15,1256.14 6223.15,1201.85 v1(6225,1200)
  Bottom Layer 1 w20: v1(6345,1735) 6345.06,1735.06 6345.06,1789.94 C90.1@6345.12,1790
  other v1: 3460,500 3520,500 3605,500 3665,500 5150,555 3250,670.16 3250,730 3250,800 5135,900 5205,900 5105,950 5170,950 5235,950 4700,1030 4700,1090 4350,1231.93 4350,1330 4450,1435 4450,1500 4450,1585 4450,1645 4385,1665 4450,1735 4385,1765 4450,1795 4450,1880 4450,1940 5480,2100 5550,2100 3250,2660 3250,2725 3250,2790
  other v2: 5445.39,523.43 5494.61,523.43 5445.39,555.12 5494.61,555.12 5532.99,555.12 5445.39,586.81 5494.61,586.81
  other v3: 2635,1960
PR12_1: C7.1 D1.2 D6.1 Q3.5 Q3.6 Q3.7 Q3.8 Q3.9@1745,2575.39 R5.1 T1.24 | length 2549.7
  Top Layer 1 w20: v1(1435,2290) R5.1@1492.44,2290
  Top Layer 1 w30: T1.24@1590,3334.92 v1(1590,3425)
  Inner Layer 2 w20: v1(1435,2290) 1511.26,2290 1547.56,2326.3 1547.56,2522.56 v1(1700,2675)
  Inner Layer 2 w30: 1590,3200 v1(1590,3425)
  Inner Layer 2 w50: 1590,3200 1590,3050 1700,2940 v1(1700,2675)
  Bottom Layer 1 w30: C7.1@890.12,3005 1500,3005 1590,3095 v1(1590,3425)
  other v1: 1775,2675
PR12_2: C19.1 D9.2 D14.1 Q7.5 Q7.6 Q7.7 Q7.8 Q7.9@1750,570.39 R21.1 T2.24 | length 2606.7
  Top Layer 1 w20: v1(1440,290) R21.1@1497.44,290
  Top Layer 1 w30: T2.24@1590,1329.96 v1(1590,1425)
  Inner Layer 2 w20: v1(1440,290) 1515.73,290 1550.06,324.33 1550.06,500.06 v1(1725,675)
  Inner Layer 2 w30: 1590,1225 v1(1590,1425)
  Inner Layer 2 w50: 1590,1225 1590,1085 1725,950 v1(1725,675)
  Bottom Layer 1 w30: C19.1@890.12,985 1523.5,985 1590,1051.5 v1(1590,1425)
  other v1: 1800,675
PR36_1: C8.1 D2.2 D7.1 Q1.5 Q1.6 Q1.7 Q1.8 Q1.9@1510,2575.39 R3.1 T1.21 | length 2301.8
  Top Layer 1 w20: v1(1675,2290) R3.1@1729.88,2290
  Top Layer 1 w30: T1.21@1440,3334.92 v1(1440,3425)
  Inner Layer 2 w30: 1440,3200 v1(1440,3425)
  Inner Layer 2 w50: 1440,3200 1440,3035 1475,3000 v1(1475,2675)
  Inner Layer 3 w20: v1(1475,2675) 1475,2375 1560,2290 v1(1675,2290)
  Bottom Layer 1 w30: C8.1@890.12,3065 1350,3065 1440,3155 v1(1440,3425)
  other v1: 1550,2675
PR36_2: C20.1 D10.2 D15.1 Q5.5 Q5.6 Q5.7 Q5.8 Q5.9@1510,570.39 R19.1 T2.21 | length 2349.8
  Top Layer 1 w20: v1(1675,290) R19.1@1732.44,290
  Top Layer 1 w30: T2.21@1440,1329.96 v1(1440,1425)
  Inner Layer 2 w30: 1440,1225 v1(1440,1425)
  Inner Layer 2 w50: 1440,1225 1440,935 1475,900 v1(1475,675)
  Inner Layer 3 w20: v1(1475,675) 1475,375 1560,290 v1(1675,290)
  Bottom Layer 1 w30: C20.1@890.12,1045 1385,1045 1440,1100 v1(1440,1425)
  other v1: 1550,675
PR45_1: C9.1 D3.2 D5.1 Q4.5 Q4.6 Q4.7 Q4.8 Q4.9@1275,2575.39 R6.1 T1.18 | length 2176.8
  Top Layer 1 w20: v1(965,2290) R6.1@1022.44,2290
  Top Layer 1 w30: T1.18@1290,3334.92 v1(1290,3450)
  Inner Layer 2 w20: v1(965,2290) 1045,2290 1080,2325 1080,2530 v1(1225,2675)
  Inner Layer 2 w30: 1290,3200 v1(1290,3450)
  Inner Layer 2 w50: 1290,3200 1290,2960 1300,2950 v1(1300,2675)
  Bottom Layer 1 w30: C9.1@890.12,3135 1240,3135 1290,3185 v1(1290,3450)
PR45_2: C21.1 D11.2 D13.1 Q8.5 Q8.6 Q8.7 Q8.8 Q8.9@1282.2,571.42 R22.1 T2.18 | length 2234.9
  Top Layer 1 w20: v1(965,285) R22.1@1022.44,285
  Top Layer 1 w30: T2.18@1290,1329.96 v1(1290,1450)
  Inner Layer 2 w20: v1(965,285) 1035,285 1075,325 1075,500 v1(1250,675)
  Inner Layer 2 w30: 1290,1225 v1(1290,1450)
  Inner Layer 2 w50: v1(1250,675) 1250,900 1290,940 1290,1225
  Bottom Layer 1 w30: C21.1@890.12,1110 1250.67,1110 1290,1149.33 v1(1290,1450)
  other v1: 1325,675
PR78_1: C10.1 D4.2 D8.1 Q2.5 Q2.6 Q2.7 Q2.8 Q2.9@1040,2575.39 R4.1 T1.15 | length 1907.3
  Top Layer 1 w20: v1(1200,2290) R4.1@1257.44,2290
  Top Layer 1 w30: T1.15@1140,3334.92 v1(1140,3425)
  Inner Layer 2 w30: 1140,3200 v1(1140,3425)
  Inner Layer 2 w50: v1(1075,2675) 1075,2950 1140,3015 1140,3200
  Inner Layer 3 w20: v1(1000,2675) 1000,2375 1085,2290 v1(1200,2290)
  Bottom Layer 1 w30: C10.1@890.12,3195 1085,3195 1140,3250 v1(1140,3425)
PR78_2: C22.1 D12.2 D16.1 Q6.5 Q6.6 Q6.7 Q6.8 Q6.9@1040,570.39 R20.1 T2.15 | length 1956.9
  Top Layer 1 w20: v1(1205,290) R20.1@1262.44,290
  Top Layer 1 w30: T2.15@1140,1329.96 v1(1140,1425)
  Inner Layer 2 w30: 1140,1225 v1(1140,1425)
  Inner Layer 2 w50: v1(1075,675) 1075,900 1140,965 1140,1225
  Inner Layer 3 w20: v1(1000,675) 1000,375 1085,290 v1(1205,290)
  Bottom Layer 1 w30: C22.1@890.12,1170 1110,1170 1140,1200 v1(1140,1425)
RTN1: C25.2 C26.2 C87.2 C89.1 C92.2 D24.3 D55.1 Q31.2 R136.1 U1.11 U1.12 U20.2 | length 411.7
  Top Layer 1 w20: v3(1820,2190) C92.2@1872.44,2190 ; R136.1@1872.44,2080 C89.1@1872.44,2025 1873.72,2023.72 1873.72,1976.28 v3(1875,1975) ; v3(1880,1820) 1880.85,1820.85 1936.75,1820.85 D55.1@1937.6,1821.69 ; Q31.2@2080.2,1905 2085.94,1910.75 2085.94,1937.16 2100,1951.21 v3(2100,1955) ; v3(2090,2245) 2090,2167.27 2101.72,2155.55 U20.2@2144.13,2155.55
  other v1: 2575,2685 2575,2755 2575,2820 2360,3125 2605,3125 2800,3125 3060,3125 3250,3125 2360,3230 2800,3230 3250,3230
RTN2: C34.2 C35.2 C88.2 D34.3 U7.11 U7.12
  other v1: 2575,725 2575,775 2575,825 2260,1110 2350,1125 2615,1125 2800,1125 3065,1125 3255,1125 2350,1235 2800,1235 3255,1235 1925,1675
SCL_PRI: J10.3 J11.2 J12.2 R116.2 R127.1 U10.5 | length 6949.8
  Top Layer 1 w10: U10.5@4424.37,528.39 4424.37,455.63 4480,400 4595,400 4620,375 J12.2@4620,325
  Top Layer 1 w20: R116.2@3913.05,3330 3914.03,3329.03 3914.03,3275.97 v1(3915,3275) ; J12.2@4620,325 J11.2@4620,150 4620,100 4645,75 4820,75 4895,150 J10.3@4900,150
  Inner Layer 3 w10: v1(3915,3275) 3915,3045 4025,2935 4025,800 4200,625 4200,325 4265,260 4605,260 4620,275 J12.2@4620,325 ; J10.3@4900,150 6025,150 6350,475 v1(6350,1260)
  Bottom Layer 1 w15: v1(6350,1260) R127.1@6350,1315
SCL_PRI_BF: R122.1 U18.2 U19.3 | length 503.2
  Bottom Layer 1 w15: U18.2@6043.7,1412.76 6092.76,1412.76 6110,1430 6110,1640 ; U19.3@6125,1788.7 6125,1728.7 6110,1713.7 6110,1640 ; R122.1@6174.88,1640 6110,1640
SCL_PRI_ISO: J13.9 R115.2 R126.2 | length 4505.2
  Top Layer 1 w20: R115.2@4515.61,3435 v1(4575,3435)
  Inner Layer 3 w10: J13.9@5000,4050 4930,3980 4930,3830 5110,3650 6340,3650 6395,3595 6395,2355 6365,2325 6235,2325 v1(6120,2210)
  Bottom Layer 1 w15: R126.2@6120,2152.56 v1(6120,2210)
  Bottom Layer 1 w20: v1(4575,3435) 4685,3435 4725,3475 4725,4025 4750,4050 J13.9@5000,4050
SDA_PRI: J10.2 J11.1 J12.1 R81.2 R129.1 U10.4 | length 8032.5
  Top Layer 1 w10: U10.4@4404.69,528.39 4404.69,570.35 4415,580.67 4435.67,580.67 4452.76,563.58 4452.76,471.02 4495.15,428.62 4683.88,428.62 4720,392.5 J12.1@4720,325
  Top Layer 1 w20: R81.2@3913.05,3510 3914.03,3509.03 3914.03,3450.97 v1(3915,3450) ; J11.1@4720,150 4720,250 ; J12.1@4720,325 4720,250 ; J10.2@4900,250 4720,250
  Inner Layer 3 w10: v1(3915,3450) 3875,3450 3850,3425 3850,3072.85 4000,2922.85 4000,790 4175,615 4175,300 4255,220 4695,220 4720,245 J12.1@4720,325 ; J11.1@4720,150 4795,75 4950,75 4975,100 6050,100 6400,450 6400,1510 v1(6350,1560)
  Bottom Layer 1 w15: R129.1@6350,1505.12 v1(6350,1560)
SDA_PRI_BF: R121.1 U18.3 U19.2 | length 780.7
  Bottom Layer 1 w15: U18.3@6043.7,1438.35 5998.96,1438.35 5978.31,1459 5978.31,1815.55 6007.76,1845 6160,1845 6174.17,1830.83 6174.17,1789.53 U19.2@6175,1788.7 6174.94,1788.64 6174.94,1695.06 R121.1@6174.88,1695
SDA_PRI_ISO: J13.10 R79.2 R125.2 | length 3630.5
  Top Layer 1 w20: R79.2@4653.17,3990 4653.17,3989.02 4658.92,3983.27 4659.9,3983.27 4693.17,3950 J13.10@5000,3950
  Inner Layer 3 w10: J13.10@5000,3950 5000,3800.96 5125.96,3675 6350,3675 6420,3605 6420,2340 6380,2300 6270,2300 v1(6180,2210)
  Bottom Layer 1 w15: R125.2@6180,2152.56 v1(6180,2210)
SS: C96.1 Q13.3 R95.2 R97.2 U14.38 | length 4226.6
  Top Layer 1 w7: U14.38@5509.37,633.86 5509.37,664.37 5550,705 5550,792.44 C96.1@5545,797.44 C96.1@5544.37,798.07
  Top Layer 1 w10: R95.2@5600,797.44 5627.5,797.44 5640,809.94 v1(5640,975)
  Top Layer 1 w20: v1(3315,2540) 3316.28,2541.28 3369.35,2541.28 Q13.3@3370.63,2542.56 ; R97.2@5488,798.7 5488.63,798.07 C96.1@5544.37,798.07 ; C96.1@5545,797.44 R95.2@5600,797.44
  Bottom Layer 1 w10: v1(3315,2540) 3315,2025 3365,1975 3575,1975 3650,1900 3650,1700 3850,1500 3850,1150 5580.37,1150 5640,1090.37 v1(5640,975)
TPH1: U1.18 U5.2 | length 1059.9
  Top Layer 1 w10: U5.2@2145,3775.98 U5.2@2145.98,3775 ; v1(2400,3025) 2425,3000 U1.18@2425,2951.54
  Top Layer 1 w20: U5.2@2145.98,3775 v1(2200,3775)
  Inner Layer 3 w10: v1(2200,3775) 2200,3772.14 2230,3742.14 2230,3045 2250,3025 v1(2400,3025)
TPH2: U6.2 U7.18 | length 4211.3
  Top Layer 1 w10: v1(2400,1025) 2425,1000 U7.18@2425,956.54 ; U6.2@2855,3775.98 U6.2@2855.98,3775
  Top Layer 1 w20: U6.2@2855.98,3775 v1(2925,3775)
  Inner Layer 3 w10: v1(2400,1025) 2400,1600 2475,1675 3101.65,1675 3148.7,1722.05 3148.7,1758.7 3325,1935 3325,2440 3265,2500 3265,2615 3300,2650 3300,2950 3425,3075 3425,3450 3400,3475 2950,3475 2925,3500 v1(2925,3775)
TPL1: U1.17 U3.2 | length 945.4
  Top Layer 1 w10: U1.17@2450.59,2951.54 2450.59,3000.59 v1(2475,3025) ; U3.2@2505,3775.98 U3.2@2505.98,3775
  Top Layer 1 w20: U3.2@2505.98,3775 v1(2575,3775)
  Inner Layer 3 w10: v1(2475,3025) 2475,3675 v1(2575,3775)
TPL2: U4.2 U7.17 | length 3836
  Top Layer 1 w10: U7.17@2450.59,956.54 2450.59,999.41 v1(2476.18,1025)
  Top Layer 1 w20: U4.2@3205,3775.98 3205.49,3775.49 3274.51,3775.49 v1(3275,3775)
  Inner Layer 3 w10: v1(2476.18,1025) 2476.18,1578.46 2522.72,1625 3148.7,1625 3202.24,1678.54 3202.24,1767.24 3375,1940 3375,2950 3475,3050 3475,3475 3425,3525 3300,3525 3275,3550 v1(3275,3775)
VB: C81.2 J15.1 R103.2 R105.2 U14.34 U14.37 | length 1619.4
  Top Layer 1 w7: U14.37@5525.56,634.3 U14.37@5525.12,633.86 5525.12,654.37 5595.75,725 v1(5650,725) ; U14.34@5564.93,586.18 U14.34@5564.49,586.61 5835.31,586.61 5850,601.3 5850,662.24 5840,672.24 5805.31,672.24 R103.2@5805,672.56
  Top Layer 1 w15: v1(5650,725) 5650,767.44 5670.77,788.21 5670.77,789.19 5679.02,797.44 C81.2@5680,797.44
  Top Layer 1 w20: R105.2@5748.84,673.84 5748.78,673.78 5803.78,673.78 R103.2@5805,672.56 v1(5805,725)
  Inner Layer 3 w20: v1(5650,725) v1(5805,725)
  Bottom Layer 1 w10: J15.1@5075,755 5146.61,755 5261.61,640 5623.35,640 5650,666.65 v1(5650,725)
VCC: C45.1 C74.2 C80.2 L9.1 U8.2 U14.42 | length 1711
  Top Layer 1 w7: C74.2@5378,798.7 5378,731.84 5446.38,663.47 U14.42@5446.38,633.86
  Top Layer 1 w20: U8.2@5223.31,281.82 5223.62,281.82 5225.43,283.63 5225.43,347.87 C45.1@5227.56,350 v1(5285,350) ; v1(5325,800) 5325.65,799.35 5377.35,799.35 C74.2@5378,798.7 ; L9.1@5722.68,1275.43 5722.89,1275.22 5799.78,1275.22 C80.2@5800,1275 v1(5800,1220)
  Inner Layer 3 w20: v1(5285,350) 5285,760 v1(5325,800) 5325,951.34 5593.66,1220 v1(5800,1220)
VDD: C2.1 C14.1 C25.1 C26.1 C27.2 C32.2 C33.2 C34.1 C35.1 C36.1 C37.1 C41.2 C57.2 C87.1 C88.1 D17.1 D18.1 D19.1 D21.1 D26.3 D27.1 D28.1 D29.1 D30.1 D37.1 L1.2 L3.2 Q11.2 Q17.2 Q30.2 R33.2 R34.2 R35.2 R36.2 R45.2 R50.1 R55.1 R56.1 R57.1 R58.1 R59.2 R60.2 R61.2 R71.1 R72.1 R84.1 R130.1 R131.2 R135.2 U1.1 U7.1 U10.8 | length 8969.6
  Top Layer 1 w10: R60.2@2200,945 2250,945 2278.82,916.18 U7.1@2333.46,916.18 ; R34.2@2200,2940 2249.98,2940 2278.8,2911.18 U1.1@2333.46,2911.18 ; C57.2@4250,610 4350,610 4385,645 U10.8@4385,701.61
  Top Layer 1 w15: R135.2@1872.44,2135 1830,2135 1815,2120 1815,1915 1865,1865 2026.38,1865 ; R130.1@2030,1975.63 2030,1868.62 2026.38,1865 ; Q30.2@2391.12,1894.13 Q30.2@2392.93,1895.94 2394.17,1897.19 2394.17,1927.01 2381.93,1939.25 2292.54,1939.25 2280.45,1927.16 D37.1@2240,1927.16 2241.73,1925.43 2241.73,1888.79 2232.95,1880 2202.76,1880 2187.76,1865 2026.38,1865 ; D27.1@2986.65,175 2986.65,256.97 3014.69,285 3029.52,285 3038.31,293.79 Q17.2@3038.31,322.4 ; D17.1@3021.65,2165 3021.65,2274.68 Q11.2@3059.37,2312.4
  Top Layer 1 w20: R57.1@1959.88,3775 1959.88,3574.43 1990,3544.31 2258.17,3544.31 C25.1@2260,3542.48 2260,3572.01 2314.88,3626.89 R55.1@2314.88,3775 ; C34.1@2260,1542.48 2361.59,1542.48 2390,1570.89 v3(2390,1780) 2388.78,1781.22 2388.78,1834.64 2391.12,1836.98 Q30.2@2391.12,1894.13 ; R58.1@2674.88,3775 2674.88,3572.6 C26.1@2705,3542.48 ; R84.1@2957.89,2062.95 2957.89,2062.36 2967.58,2052.68 3017.32,2052.68 v3(3020,2050) 3020,2163.19 3020.45,2163.64 3021.65,2163.64 D17.1@3021.65,2165 ; R56.1@3014.88,3775 3014.88,3573.7 3046.1,3542.48 C87.1@3155,3542.48 ; R36.2@3022.56,2450 3022.11,2449.55 3022.11,2385.45 D18.1@3021.65,2385 3065,2385 v1(3100,2350) 3100,2311.3 ; Q11.2@3063.31,2311.3 3100,2311.3 ; v1(3070,460) R61.2@3002.56,460 3002.11,459.55 3002.11,395.45 D28.1@3001.65,395 3001.65,355.12 3034.37,322.4 Q17.2@3038.31,322.4 3084.17,322.4 3099.02,307.56 R59.2@3100,307.56 ; D21.1@3082.01,2975 3763.61,2975 3937.69,2800.92 3937.69,2661.77 3890.92,2615 v1(3650,2615) 3649.94,2615.06 3590.06,2615.06 R45.2@3590,2615.12 ; R35.2@3130,2297.56 3129.02,2297.56 3115.28,2311.3 3100,2311.3 ; R33.2@3670,2275.12 3670.06,2275.06 v1@3729.94,2275.06 ; R50.1@3727.56,2357.56 3728.78,2356.34 3728.78,2276.22 v1@3729.94,2275.06 ; D26.3@3823.78,746.77 3825.55,745 4188.28,745 4200,733.28 4200,660 4228.5,631.5 4228.5,625 4243.5,610 C57.2@4250,610 ; C36.1@3947.52,1715 3947.52,2163.72 3836.24,2275 v1(3730,2275) v1@3729.94,2275.06 ; R72.1@4335,937.56 4335.31,937.87 4335.31,1029.68 R71.1@4335.63,1030
  Top Layer 1 w25: C41.2@2100,909.37 2104.92,909.37 2140.55,945 R60.2@2200,945 ; C27.2@2100,2904.37 2104.92,2904.37 2140.55,2940 R34.2@2200,2940
  Inner Layer 3 w10: v3(2390,1780) 2475,1865 2960,1865 2975,1880 2975,2005 v3(3020,2050) ; v1(3070,460) 3180,570 v1(3180,935)
  other v1: 2000,1075 2060,1075 2125,1075 1985,3075 2055,3075 2125,3075
VDD_PM: C58.1 C75.1 L7.1 R71.2 R73.1 R95.1 R110.1 U14.23 | length 2278
  Top Layer 1 w7: U14.23@5564.49,397.64 5593.66,397.64 5625,366.3 C75.1@5625,329.37
  Top Layer 1 w20: R95.1@5600,852.56 v1(5600,915) ; C75.1@5625,329.37 5789.37,329.37 5810,350 v1(5810,385) R110.1@5747.56,385
  Bottom Layer 1 w10: v1(4500,950) 4750,950 4825,1025 5348.81,1025 5398.81,975 5575,975 5600,950 v1(5600,915) 5600,883.78 5720,763.78 5720,475 v1(5810,385)
VOUT: C47.1 C65.1 C66.1 C67.1 C68.2 C69.2 C70.2 J14.1 L8.2 R53.2 R70.1 R101.1 U9.2 | length 5276.4
  Top Layer 1 w15: R53.2@3507.44,4100 3507.44,4147.44 3550,4190 6350,4190 6439.41,4100.59 6439.41,3827.73 6411.68,3800 J14.1@6340,3800
  Top Layer 1 w20: R101.1@6270,2462.56 6387.56,2462.56 6425,2500 6425,3715 J14.1@6340,3800
  Bottom Layer 1 w15: R70.1@6218.74,3935.44 6210.49,3927.19 6199.76,3927.19 6193.17,3920.6 U9.2@6150.98,3920.6 6151.14,3920.44 6151.14,3853.16 C47.1@6151.3,3853 6151.3,3852.02 6159.54,3843.77 6160.53,3843.77 6204.3,3800 J14.1@6340,3800
VSS_1: C2.2 C27.1 D19.2 L2.2 R40.2 R44.2 R46.1 R47.1 R48.1 U1.4 U1.5 U1.21@2425,2860 | length 61.1
  Top Layer 1 w20: v1(2450,2565) 2450,2568.18 2465,2583.18 R40.2@2465,2619.88
  other v1: 1990,2700 2050,2700 2120,2700 2275,2775
  other v2: 2425,2826.54 2391.54,2860 2425,2860 2458.46,2860 2425,2893.46
VSS_2: C14.2 C41.1 D29.2 L4.2 R64.2 R65.2 R66.1 R67.1 R68.1 U7.4 U7.5 U7.21@2425,865 | length 66.1
  Top Layer 1 w20: v1(2450,575) 2450,578.18 2465,593.18 R64.2@2465,634.88
  other v1: 2000,690 2060,690 2125,690 2270.55,775
  other v2: 2425,831.54 2391.54,865 2425,865 2458.46,865 2425,898.46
